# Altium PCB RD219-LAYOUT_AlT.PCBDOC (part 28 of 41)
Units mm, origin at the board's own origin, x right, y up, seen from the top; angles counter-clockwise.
Board outline 209.75 x 159.97 mm, 2 copper layers (TOP, BOTTOM), stack 0 mm thick; 398 components, 199 nets, 1469 pads, 0 vias.
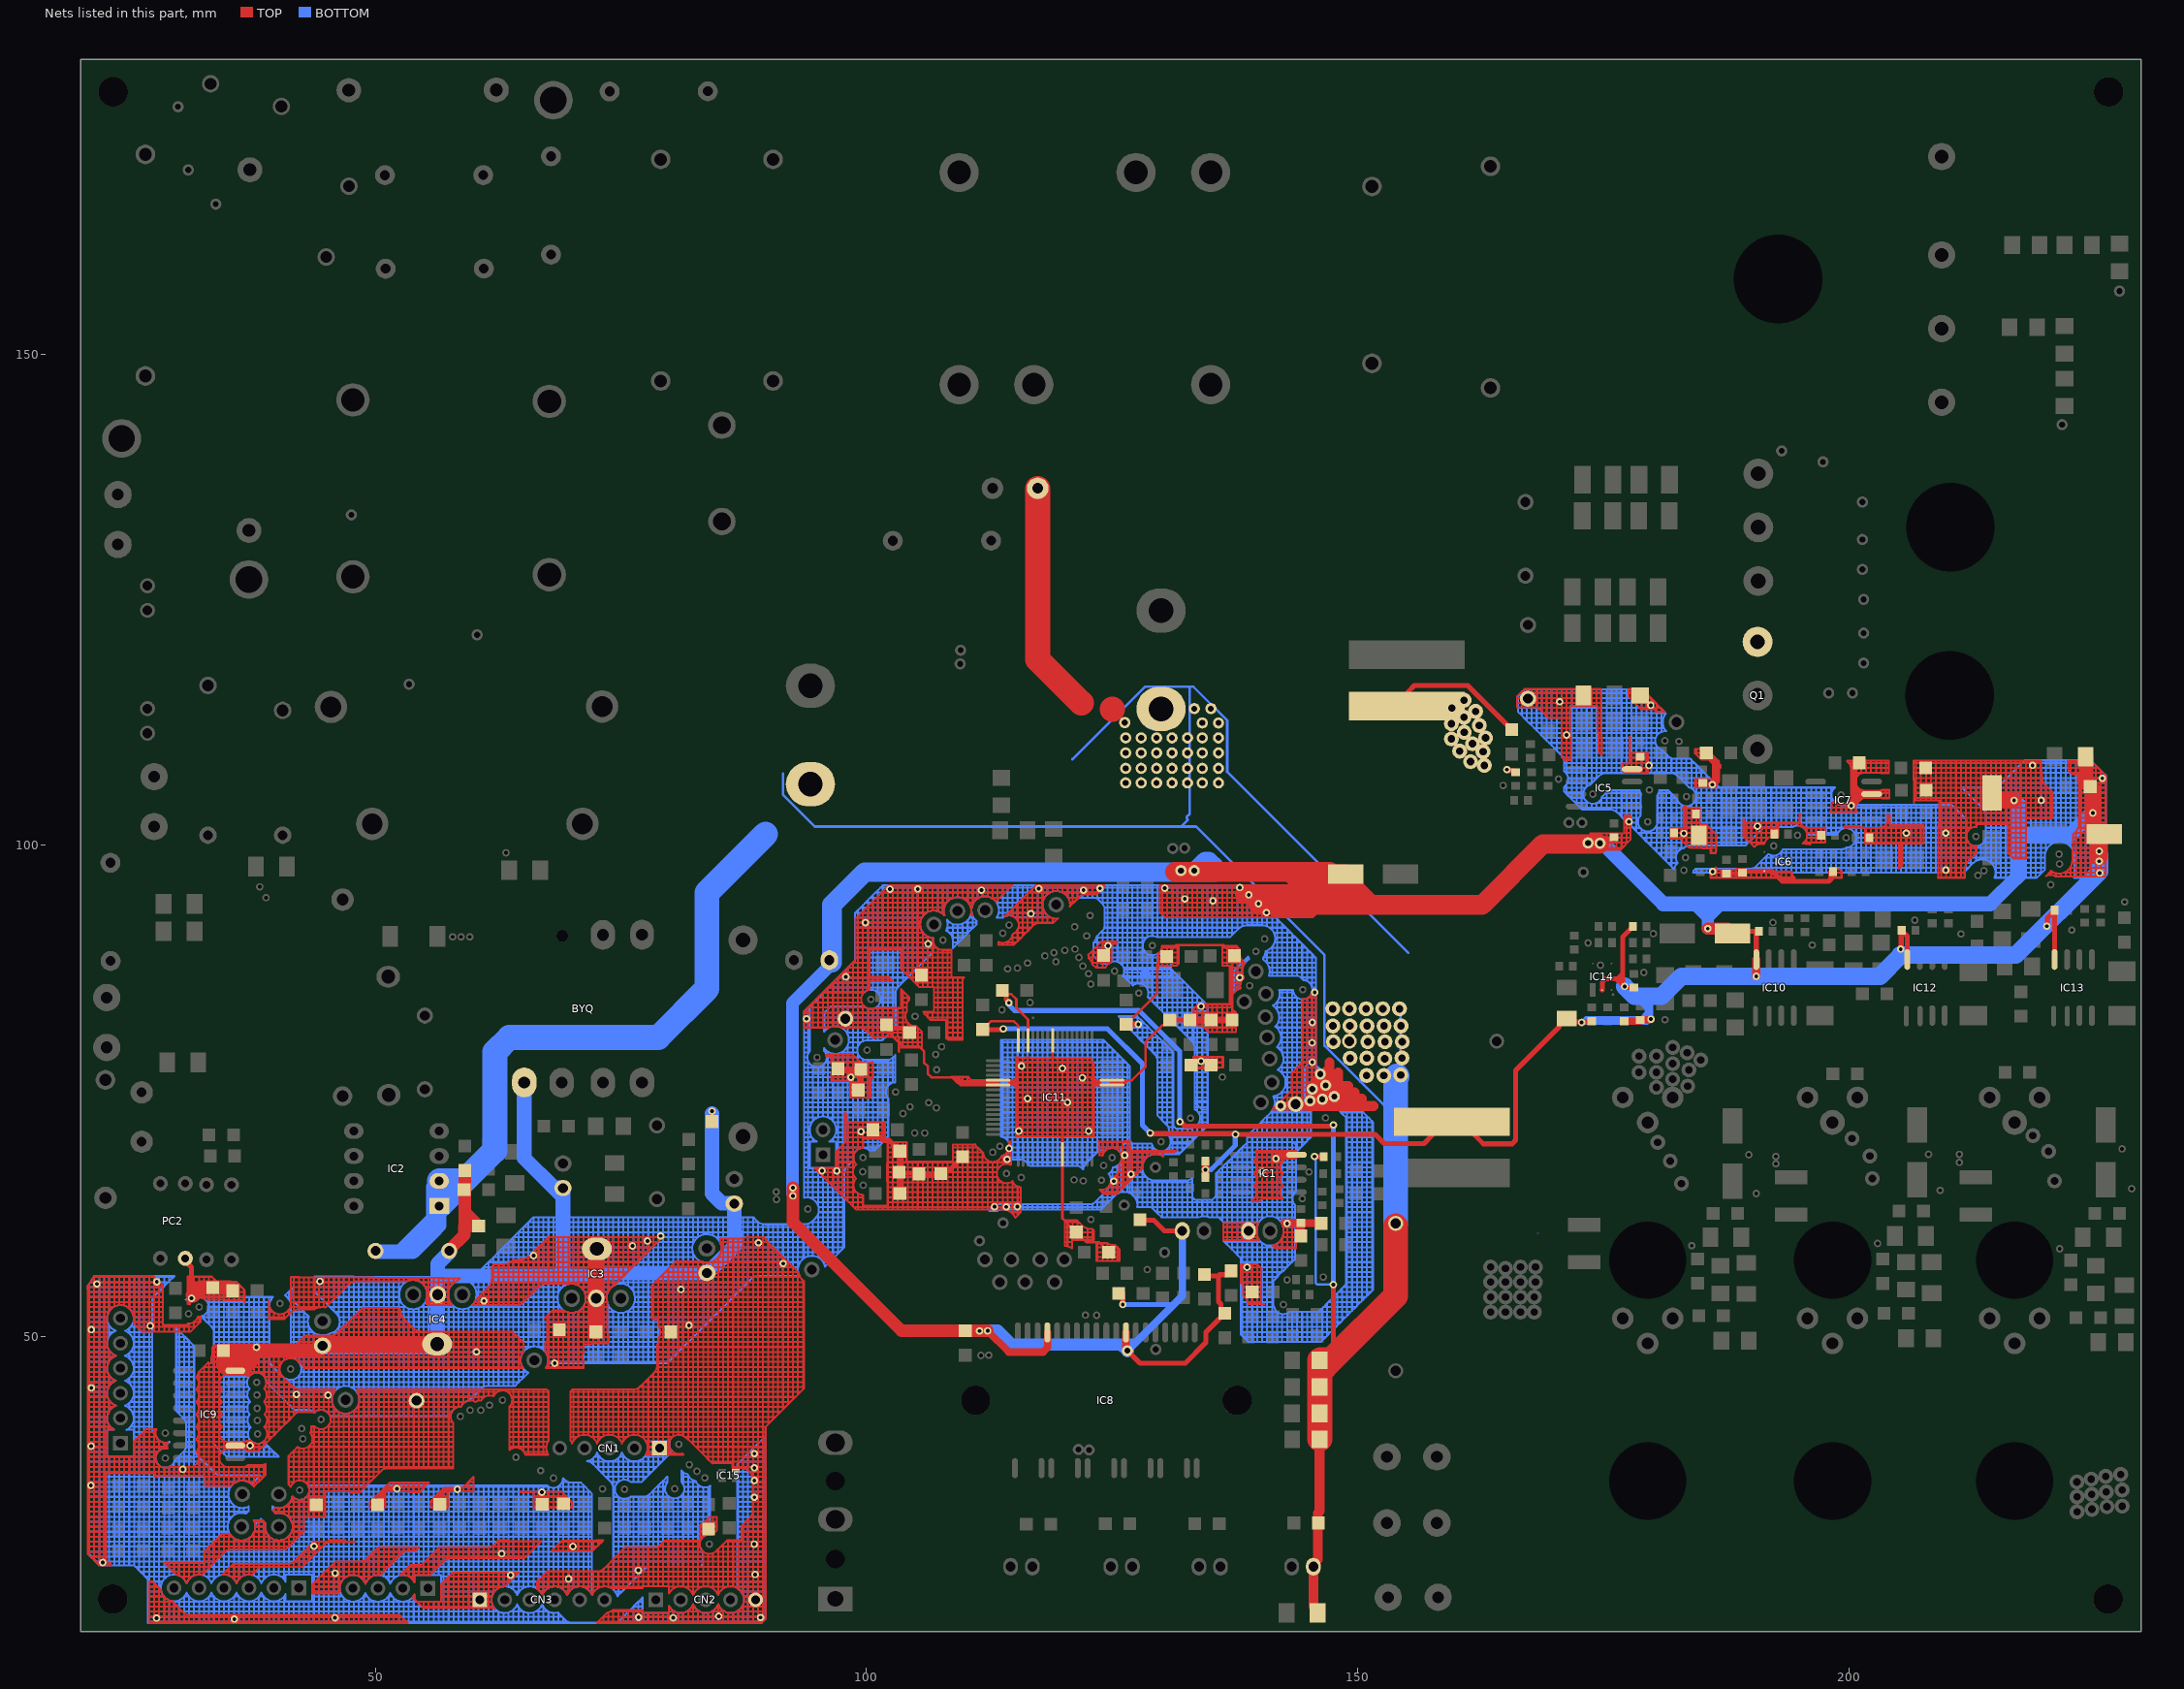
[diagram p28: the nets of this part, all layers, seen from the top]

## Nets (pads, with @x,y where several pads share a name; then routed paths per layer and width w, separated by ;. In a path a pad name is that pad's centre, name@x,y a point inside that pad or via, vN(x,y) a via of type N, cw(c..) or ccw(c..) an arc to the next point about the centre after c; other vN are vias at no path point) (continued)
GND: (continued)
  BOTTOM w0.203: 79.817,32.7 79.817,33.208 ; 79.817,32.7 80.325,32.7 ; 79.817,33.208 79.817,33.716 ; 79.817,33.208 80.325,33.208 ; 79.817,33.716 79.93,33.716 ; 79.817,33.716 79.817,33.804 ; 79.817,33.804 ccw(c80.475,34.534) 79.93,33.716 ; 79.817,37.921 79.817,38.288 ; 79.817,38.288 79.817,38.796 ; 79.817,38.796 79.817,39.304 ; 79.817,38.796 79.946,38.796 ; 79.817,39.304 79.817,39.337 ; 79.817,39.304 79.945,39.304 ; 79.817,39.337 79.955,39.337 ccw(c80.895,39.051) 79.945,39.304 ; 79.817,47.405 79.817,47.432 ; 79.817,47.405 79.844,47.432 ; 79.817,47.432 79.817,47.94 ; 79.817,47.432 79.844,47.432 ; 79.817,47.94 80.325,47.94 ; 79.817,47.94 79.817,48.448 ; 79.817,48.448 79.817,48.956 ; 79.817,48.448 80.325,48.448 ; 79.817,48.956 79.817,49.464 ; 79.817,48.956 80.325,48.956 ; 79.817,49.464 79.817,49.972 ; 79.817,49.464 80.325,49.464 ; 79.817,49.972 79.817,50.48 ; 79.817,49.972 80.325,49.972 ; 79.817,50.48 79.817,50.988 ; 79.817,50.48 80.325,50.48 ; 79.817,50.988 79.817,51.496 ; 79.817,50.988 80.325,50.988 ; 79.817,51.496 79.817,52.004 ; 79.817,51.496 80.325,51.496 ; 79.817,52.004 79.817,52.512 ; 79.817,52.004 80.325,52.004 ; 79.817,52.512 80.325,52.512 ; 79.817,52.512 79.817,53.02 ; 79.817,53.02 79.817,53.528 ; 79.817,53.02 80.325,53.02 ; 79.817,53.528 79.817,54.036 ; 79.817,53.528 80.325,53.528 ; 79.817,54.036 80.325,54.036 ; 79.817,54.036 79.817,54.544 ; 79.817,54.544 79.817,55.052 ; 79.817,54.544 80.325,54.544 ; 79.817,55.052 79.817,55.56 ; 79.817,55.052 80.325,55.052 ; 79.817,55.56 79.817,56.068 ; 79.817,55.56 80.325,55.56 ; 79.817,56.068 80.325,56.068 ; 79.817,56.068 79.817,56.489 79.817,56.576 ; 79.817,56.576 80.325,56.576 ; 79.817,56.576 79.817,57.084 ; 79.817,57.084 80.325,57.084 ; 79.817,57.084 79.817,57.592 ; 79.817,57.592 80.325,57.592 ; 79.817,57.592 79.817,58.1 ; 79.817,58.1 79.817,58.608 ; 79.817,58.1 80.325,58.1 ; 79.817,58.608 79.817,59.116 ; 79.817,58.608 80.325,58.608 ; 79.817,59.116 79.817,59.624 ; 79.817,59.116 80.325,59.116 ; 79.817,59.624 79.817,60.132 ; 79.817,59.624 80.325,59.624 ; 79.817,60.132 79.817,60.64 ; 79.817,60.132 80.325,60.132 ; 79.817,60.64 79.817,61.148 ; 79.817,60.64 80.325,60.64 ; 79.817,61.148 79.817,61.656 ; 79.817,61.148 80.325,61.148 ; 79.817,61.656 79.817,62.164 ; 79.817,61.656 80.325,61.656 ; 79.817,62.164 80.325,62.164 ; 79.844,47.432 80.325,47.913 ; 79.899,22.032 80.325,22.032 ; 79.899,22.032 79.899,22.597 ; 79.899,22.597 ccw(c81.087,23.241) 80.325,22.125 ; 79.93,33.716 ccw(c80.475,34.534) 80.322,33.563 ccw(c80.475,34.534) 80.325,33.563 ; 79.946,38.796 cw(c80.895,39.051) 79.945,39.304 ; 80.325,20.889 80.325,21.016 ; 80.325,20.889 80.833,20.889 ; 80.325,21.016 pad.@80.325,21.524 ; 80.325,21.016 80.833,21.016 ; pad.@80.325,21.524 80.325,22.032 ; pad.@80.325,21.524 80.833,21.524 ; 80.325,22.032 80.483,22.032 ; 80.325,22.032 80.325,22.125 ; 80.325,22.125 ccw(c81.087,23.241) 80.483,22.032 ; 80.325,26.571 80.325,26.604 ; 80.325,26.571 80.833,26.571 ; 80.325,26.604 80.325,27.112 ; 80.325,26.604 80.833,26.604 ; 80.325,27.112 80.325,27.62 ; 80.325,27.112 80.833,27.112 ; 80.325,27.62 80.325,28.128 ; 80.325,27.62 80.833,27.62 ; 80.325,28.128 80.325,28.636 ; 80.325,28.128 80.833,28.128 ; 80.325,28.636 80.325,29.144 ; 80.325,28.636 80.833,28.636 ; 80.325,29.144 80.325,29.652 ; 80.325,29.144 80.833,29.144 ; 80.325,29.652 80.325,30.16 ; 80.325,29.652 80.833,29.652 ; 80.325,30.16 80.325,30.668 ; 80.325,30.16 80.833,30.16 ; 80.325,30.668 80.325,31.176 ; 80.325,30.668 80.833,30.668 ; 80.325,31.176 80.325,31.684 ; 80.325,31.176 80.833,31.176 ; 80.325,31.684 80.325,32.192 ; 80.325,31.684 80.833,31.684 ; 80.325,32.192 80.325,32.7 ; 80.325,32.192 80.833,32.192 ; 80.325,32.7 80.325,33.208 ; 80.325,32.7 80.833,32.7 ; 80.325,33.208 80.833,33.208 ; 80.325,33.208 80.325,33.563 ; 80.325,33.563 ccw(c80.475,34.534) 80.827,33.616 ccw(c80.475,34.534) 80.833,33.618 ; 80.325,47.913 80.325,47.94 ; 80.325,47.913 80.352,47.94 ; 80.325,47.94 80.325,48.448 ; 80.325,47.94 80.352,47.94 ; 80.325,48.448 80.833,48.448 ; 80.325,48.448 80.325,48.956 ; 80.325,48.956 80.325,49.464 ; 80.325,48.956 80.833,48.956 ; 80.325,49.464 80.325,49.972 ; 80.325,49.464 80.833,49.464 ; 80.325,49.972 80.325,50.48 ; 80.325,49.972 80.833,49.972 ; 80.325,50.48 80.325,50.988 ; 80.325,50.48 80.833,50.48 ; 80.325,50.988 80.325,51.496 ; 80.325,50.988 80.833,50.988 ; 80.325,51.496 80.325,52.004 ; 80.325,51.496 80.833,51.496 ; 80.325,52.004 80.325,52.512 ; 80.325,52.004 80.833,52.004 ; 80.325,52.512 80.325,53.02 ; 80.325,52.512 80.833,52.512 ; 80.325,53.02 80.325,53.528 ; 80.325,53.02 80.833,53.02 ; 80.325,53.528 80.325,54.036 ; 80.325,53.528 80.833,53.528 ; 80.325,54.036 80.325,54.544 ; 80.325,54.036 80.833,54.036 ; 80.325,54.544 80.325,55.052 ; 80.325,54.544 80.833,54.544 ; 80.325,55.052 80.325,55.56 ; 80.325,55.052 pad.@80.833,55.052 ; 80.325,55.56 80.325,56.068 ; 80.325,55.56 80.833,55.56 ; 80.325,56.068 80.325,56.489 80.325,56.576 ; 80.325,56.068 80.833,56.068 ; 80.325,56.576 80.325,57.084 ; 80.325,56.576 80.833,56.576 ; 80.325,57.084 80.325,57.592 ; 80.325,57.084 80.833,57.084 ; 80.325,57.592 80.325,58.1 ; 80.325,57.592 80.833,57.592 ; 80.325,58.1 80.325,58.608 ; 80.325,58.1 80.833,58.1 ; 80.325,58.608 80.325,59.116 ; 80.325,58.608 80.833,58.608 ; 80.325,59.116 80.325,59.624 ; 80.325,59.116 80.833,59.116 ; 80.325,59.624 80.325,60.132 ; 80.325,59.624 80.833,59.624 ; 80.325,60.132 80.325,60.64 ; 80.325,60.132 80.833,60.132 ; 80.325,60.64 80.325,61.148 ; 80.325,60.64 80.833,60.64 ; 80.325,61.148 80.325,61.656 ; 80.325,61.148 80.833,61.148 ; 80.325,61.656 80.325,62.164 ; 80.325,61.656 80.833,61.656 ; 80.325,62.164 80.833,62.164 ; 80.352,47.94 80.833,48.421 ; 80.483,22.032 ccw(c81.087,23.241) 80.829,21.914 ccw(c81.087,23.241) 80.833,21.914 ; 80.833,20.889 80.833,21.016 ; 80.833,20.889 81.341,20.889 ; 80.833,21.016 80.833,21.524 ; 80.833,21.016 81.341,21.016 ; 80.833,21.524 81.341,21.524 ; 80.833,21.524 80.833,21.913 ; 80.833,21.914 ccw(c81.087,23.241) 81.341,21.913 ; 80.833,26.571 80.833,26.604 ; 80.833,26.571 81.341,26.571 ; 80.833,26.604 80.833,27.112 ; 80.833,26.604 81.341,26.604 ; 80.833,27.112 80.833,27.62 ; 80.833,27.112 81.341,27.112 ; 80.833,27.62 80.833,28.128 ; 80.833,27.62 81.341,27.62 ; 80.833,28.128 80.833,28.636 ; 80.833,28.128 81.341,28.128 ; 80.833,28.636 80.833,29.144 ; 80.833,28.636 81.341,28.636 ; 80.833,29.144 80.833,29.652 ; 80.833,29.144 81.341,29.144 ; 80.833,29.652 80.833,30.16 ; 80.833,29.652 81.341,29.652 ; 80.833,30.16 80.833,30.668 ; 80.833,30.16 81.341,30.16 ; 80.833,30.668 80.833,31.176 ; 80.833,30.668 81.341,30.668 ; 80.833,31.176 80.833,31.684 ; 80.833,31.176 81.341,31.176 ; 80.833,31.684 80.833,32.192 ; 80.833,31.684 81.341,31.684 ; 80.833,32.192 80.833,32.7 ; 80.833,32.192 81.341,32.192 ; 80.833,32.7 80.833,33.208 ; 80.833,32.7 81.341,32.7 ; 80.833,33.208 81.341,33.208 ; 80.833,33.208 80.833,33.618 ; 80.833,48.421 80.833,48.448 ; 80.833,48.421 80.86,48.448 ; 80.833,48.448 80.833,48.956 ; 80.833,48.448 80.86,48.448 ; 80.833,48.956 81.341,48.956 ; 80.833,48.956 80.833,49.464 ; 80.833,49.464 80.833,49.972 ; 80.833,49.464 81.341,49.464 ; 80.833,49.972 80.833,50.48 ; 80.833,49.972 81.341,49.972 ; 80.833,50.48 80.833,50.988 ; 80.833,50.48 81.341,50.48 ; 80.833,50.988 80.833,51.496 ; 80.833,50.988 81.341,50.988 ; 80.833,51.496 80.833,52.004 ; 80.833,51.496 81.341,51.496 ; 80.833,52.004 80.833,52.512 ; 80.833,52.004 81.341,52.004 ; 80.833,52.512 80.833,53.02 ; 80.833,52.512 81.341,52.512 ; 80.833,53.02 80.833,53.528 ; 80.833,53.02 81.341,53.02 ; 80.833,53.528 80.833,54.036 ; 80.833,53.528 81.341,53.528 ; 80.833,54.036 80.833,54.544 ; 80.833,54.036 81.341,54.036 ; 80.833,54.544 pad.@81.341,54.544 ; 80.833,54.544 pad.@80.833,55.052 ; pad.@80.833,55.052 80.833,55.56 ; pad.@80.833,55.052 pad.@81.341,55.052 ; 80.833,55.56 80.833,56.068 ; 80.833,55.56 81.341,55.56 ; 80.833,56.068 80.833,56.489 80.833,56.576 ; 80.833,56.068 81.341,56.068 ; 80.833,56.576 80.833,57.084 ; 80.833,56.576 81.341,56.576 ; 80.833,57.084 80.833,57.592 ; 80.833,57.084 81.341,57.084 ; 80.833,57.592 80.833,58.1 ; 80.833,57.592 81.341,57.592 ; 80.833,58.1 80.833,58.608 ; 80.833,58.1 81.341,58.1 ; 80.833,58.608 80.833,59.116 ; 80.833,58.608 81.341,58.608 ; 80.833,59.116 80.833,59.624 ; 80.833,59.116 81.341,59.116 ; 80.833,59.624 80.833,60.132 ; 80.833,59.624 81.341,59.624 ; 80.833,60.132 80.833,60.64 ; 80.833,60.132 81.341,60.132 ; 80.833,60.64 80.833,61.148 ; 80.833,60.64 81.341,60.64 ; 80.833,61.148 80.833,61.656 ; 80.833,61.148 81.341,61.148 ; 80.833,61.656 80.833,62.164 ; 80.833,61.656 81.341,61.656 ; 80.833,62.164 81.341,62.164 ; 80.86,48.448 81.341,48.929 ; 81.181,35.24 81.341,35.24 ; 81.181,35.24 81.181,35.748 ; 81.181,35.748 81.341,35.748 ; 81.181,35.748 81.181,36.256 ; 81.181,36.256 81.301,36.256 ; 81.301,36.256 ccw(c81.967,36.978) 81.341,36.221 ; 81.341,20.889 81.341,21.016 ; 81.341,20.889 81.849,20.889 ; 81.341,21.016 81.341,21.524 ; 81.341,21.016 81.849,21.016 ; 81.341,21.524 81.849,21.524 ; 81.341,21.524 81.341,21.913 ; 81.341,21.913 ccw(c81.087,23.241) 81.345,21.914 ccw(c81.087,23.241) 81.691,22.032 ; 81.341,26.571 81.849,26.571 ; 81.341,26.571 81.341,26.604 ; 81.341,26.604 81.849,26.604 ; 81.341,26.604 81.341,27.112 ; 81.341,27.112 81.341,27.62 ; 81.341,27.112 81.849,27.112 ; 81.341,27.62 81.341,28.128 ; 81.341,27.62 81.849,27.62 ; 81.341,28.128 81.849,28.128 ; 81.341,28.128 81.341,28.636 ; 81.341,28.636 81.341,29.144 ; 81.341,28.636 81.849,28.636 ; 81.341,29.144 81.341,29.652 ; 81.341,29.144 81.849,29.144 ; 81.341,29.652 81.849,29.652 ; 81.341,29.652 81.341,30.16 ; 81.341,30.16 81.341,30.668 ; 81.341,30.16 81.849,30.16 ; 81.341,30.668 81.341,31.176 ; 81.341,30.668 81.849,30.668 ; 81.341,31.176 81.341,31.684 ; 81.341,31.176 81.849,31.176 ; 81.341,31.684 81.341,32.192 ; 81.341,31.684 81.849,31.684 ; 81.341,32.192 81.341,32.7 ; 81.341,32.192 81.849,32.192 ; 81.341,32.7 81.341,33.208 ; 81.341,32.7 81.849,32.7 ; 81.341,33.208 81.341,33.716 ; 81.341,33.208 81.849,33.208 ; 81.341,33.716 81.849,33.716 ; 81.341,33.716 81.341,34.069 ; 81.341,34.069 ccw(c80.475,34.534) 81.408,34.224 ; 81.341,34.998 cw(c80.475,34.534) 81.438,34.732 ; 81.341,34.998 81.341,35.24 ; 81.341,35.24 81.341,35.748 ; 81.341,35.24 81.849,35.24 ; 81.341,35.748 81.849,35.748 ; 81.341,35.748 81.341,36.221 ; 81.341,48.929 81.368,48.956 ; 81.341,48.929 81.341,48.956 ; 81.341,48.956 81.368,48.956 ; 81.341,48.956 81.341,49.464 ; 81.341,49.464 81.849,49.464 ; 81.341,49.464 81.341,49.972 ; 81.341,49.972 81.341,50.48 ; 81.341,49.972 81.849,49.972 ; 81.341,50.48 81.341,50.988 ; 81.341,50.48 81.849,50.48 ; 81.341,50.988 81.341,51.496 ; 81.341,50.988 pad.@81.849,50.988 ; 81.341,51.496 81.341,52.004 ; 81.341,51.496 pad.@81.849,51.496 ; 81.341,52.004 81.341,52.512 ; 81.341,52.004 81.849,52.004 ; 81.341,52.512 81.341,53.02 ; 81.341,52.512 81.849,52.512 ; 81.341,53.02 81.341,53.528 ; 81.341,53.02 81.849,53.02 ; 81.341,53.528 81.341,54.036 ; 81.341,53.528 81.849,53.528 ; 81.341,54.036 pad.@81.341,54.544 ; 81.341,54.036 81.849,54.036 ; pad.@81.341,54.544 81.849,54.544 ; pad.@81.341,54.544 pad.@81.341,55.052 ; pad.@81.341,55.052 81.341,55.56 ; pad.@81.341,55.052 81.849,55.052 ; 81.341,55.56 81.341,56.068 ; 81.341,55.56 81.849,55.56 ; 81.341,56.068 81.341,56.489 81.341,56.576 ; 81.341,56.068 81.849,56.068 ; 81.341,56.576 81.341,57.084 ; 81.341,56.576 81.849,56.576 ; 81.341,57.084 81.341,57.592 ; 81.341,57.084 81.849,57.084 ; 81.341,57.592 81.341,58.1 ; 81.341,57.592 81.849,57.592 ; 81.341,58.1 81.341,58.608 ; 81.341,58.1 81.849,58.1 ; 81.341,58.608 81.341,59.116 ; 81.341,58.608 81.849,58.608 ; 81.341,59.116 81.341,59.624 ; 81.341,59.116 81.849,59.116 ; 81.341,59.624 81.341,60.132 ; 81.341,59.624 81.849,59.624 ; 81.341,60.132 81.341,60.64 ; 81.341,60.132 81.849,60.132 ; 81.341,60.64 81.341,61.148 ; 81.341,60.64 81.849,60.64 ; 81.341,61.148 81.341,61.656 ; 81.341,61.148 81.849,61.148 ; 81.341,61.656 81.341,62.164 ; 81.341,61.656 81.849,61.656 ; 81.341,62.164 81.849,62.164 ; 81.368,48.956 81.849,49.437 ; 81.408,34.224 ccw(c80.475,34.534) 81.41,34.23 ccw(c80.475,34.534) 81.458,34.534 ccw(c80.475,34.534) 81.438,34.732 ; 81.408,34.224 81.849,34.224 ; 81.438,34.732 81.849,34.732 ; 81.691,22.032 ccw(c81.087,23.241) 81.843,22.12 ccw(c81.087,23.241) 81.849,22.125 ; 81.691,22.032 81.849,22.032 ; 81.849,20.889 82.357,20.889 ; 81.849,20.889 81.849,21.016 ; 81.849,21.016 82.357,21.016 ; 81.849,21.016 81.849,21.524 ; 81.849,21.524 81.849,22.032 ; 81.849,21.524 82.357,21.524 ; 81.849,22.032 82.357,22.032 ; 81.849,22.032 81.849,22.125 ; 81.849,26.571 81.849,26.604 ; 81.849,26.571 82.357,26.571 ; 81.849,26.604 82.357,26.604 ; 81.849,26.604 81.849,27.112 ; 81.849,27.112 81.849,27.62 ; 81.849,27.112 82.357,27.112 ; 81.849,27.62 81.849,28.128 ; 81.849,27.62 82.357,27.62 ; 81.849,28.128 81.849,28.636 ; 81.849,28.128 82.357,28.128 ; 81.849,28.636 81.849,29.144 ; 81.849,28.636 82.357,28.636 ; 81.849,29.144 81.849,29.652 ; 81.849,29.144 82.357,29.144 ; 81.849,29.652 82.357,29.652 ; 81.849,29.652 81.849,30.16 ; 81.849,30.16 81.849,30.668 ; 81.849,30.16 82.357,30.16 ; 81.849,30.668 81.849,31.176 ; 81.849,30.668 82.357,30.668 ; 81.849,31.176 81.849,31.684 ; 81.849,31.176 82.357,31.176 ; 81.849,31.684 81.849,32.192 ; 81.849,31.684 82.357,31.684 ; 81.849,32.192 81.849,32.7 ; 81.849,32.192 82.357,32.192 ; 81.849,32.7 81.849,33.208 ; 81.849,32.7 82.357,32.7 ; 81.849,33.208 81.849,33.716 ; 81.849,33.208 82.357,33.208 ; 81.849,33.716 81.849,34.224 ; 81.849,33.716 82.357,33.716 ; 81.849,34.224 81.849,34.732 ; 81.849,34.224 82.357,34.224 ; 81.849,34.732 82.357,34.732 ; 81.849,34.732 81.849,35.24 ; 81.849,35.24 82.357,35.24 ; 81.849,35.24 81.849,35.748 ; 81.849,35.748 81.849,35.89 ; 81.849,35.748 81.931,35.748 ; 81.849,35.89 ccw(c82.737,36.311) 81.931,35.748 ; 81.849,49.437 81.876,49.464 ; 81.849,49.437 81.849,49.464 ; 81.849,49.464 81.876,49.464 ; 81.849,49.464 81.849,49.972 ; 81.849,49.972 82.357,49.972 ; 81.849,49.972 81.849,50.48 ; 81.849,50.48 pad.@81.849,50.988 ; 81.849,50.48 82.357,50.48 ; pad.@81.849,50.988 pad.@81.849,51.496 ; pad.@81.849,50.988 82.357,50.988 ; pad.@81.849,51.496 81.849,52.004 ; pad.@81.849,51.496 82.357,51.496 ; 81.849,52.004 81.849,52.512 ; 81.849,52.004 82.357,52.004 ; 81.849,52.512 81.849,53.02 ; 81.849,52.512 82.357,52.512 ; 81.849,53.02 81.849,53.528 ; 81.849,53.02 82.357,53.02 ; 81.849,53.528 81.849,54.036 ; 81.849,53.528 82.357,53.528 ; 81.849,54.036 81.849,54.544 ; 81.849,54.036 82.357,54.036 ; 81.849,54.544 81.849,55.052 ; 81.849,54.544 82.357,54.544 ; 81.849,55.052 81.849,55.56 ; 81.849,55.052 82.357,55.052 ; 81.849,55.56 81.849,56.068 ; 81.849,55.56 82.357,55.56 ; 81.849,56.068 81.849,56.489 81.849,56.576 ; 81.849,56.068 82.357,56.068 ; 81.849,56.576 81.849,57.084 ; 81.849,56.576 82.357,56.576 ; 81.849,57.084 81.849,57.592 ; 81.849,57.084 82.357,57.084 ; 81.849,57.592 81.849,58.1 ; 81.849,57.592 82.357,57.592 ; 81.849,58.1 81.849,58.608 ; 81.849,58.1 82.357,58.1 ; 81.849,58.608 81.849,59.116 ; 81.849,58.608 82.315,58.608 ; 81.849,59.116 81.849,59.624 ; 81.849,59.116 82.269,59.116 ; 81.849,59.624 82.357,59.624 ; 81.849,59.624 81.849,60.132 ; 81.849,60.132 81.849,60.64 ; 81.849,60.132 82.357,60.132 ; 81.849,60.64 81.849,61.148 ; 81.849,60.64 82.357,60.64 ; 81.849,61.148 81.849,61.656 ; 81.849,61.148 82.357,61.148 ; 81.849,61.656 81.849,62.164 ; 81.849,61.656 82.357,61.656 ; 81.849,62.164 82.357,62.164 ; 81.876,49.464 82.357,49.945 ; 81.931,35.748 ccw(c82.737,36.311) 82.353,35.406 ccw(c82.737,36.311) 82.357,35.405 ; 82.269,59.116 ccw(c83.691,58.989) 82.269,59.113 ccw(c83.691,58.989) 82.315,58.608 ; 82.269,59.116 cw(c83.691,58.989) 82.357,59.497 ; 82.315,58.608 ccw(c83.691,58.989) 82.357,58.481 ; 82.357,20.889 82.357,21.016 ; 82.357,20.889 82.865,20.889 ; 82.357,21.016 82.357,21.524 ; 82.357,21.016 82.865,21.016 ; 82.357,21.524 82.357,22.032 ; 82.357,21.524 82.865,21.524 ; 82.357,22.032 82.865,22.032 ; 82.357,22.032 82.357,22.54 ; 82.357,22.54 82.471,22.54 ; 82.357,22.54 82.357,22.778 ; 82.357,22.778 ccw(c83.627,23.241) 82.468,22.545 ccw(c83.627,23.241) 82.471,22.54 ; 82.357,26.571 82.357,26.604 ; 82.357,26.571 82.865,26.571 ; 82.357,26.604 82.357,27.112 ; 82.357,26.604 82.865,26.604 ; 82.357,27.112 82.357,27.62 ; 82.357,27.112 82.865,27.112 ; 82.357,27.62 82.357,28.128 ; 82.357,27.62 82.865,27.62 ; 82.357,28.128 82.357,28.636 ; 82.357,28.128 82.865,28.128 ; 82.357,28.636 82.357,29.144 ; 82.357,28.636 82.865,28.636 ; 82.357,29.144 82.357,29.652 ; 82.357,29.144 82.865,29.144 ; 82.357,29.652 82.357,30.16 ; 82.357,29.652 82.865,29.652 ; 82.357,30.16 82.357,30.668 ; 82.357,30.16 82.865,30.16 ; 82.357,30.668 82.357,31.176 ; 82.357,30.668 82.865,30.668 ; 82.357,31.176 82.357,31.684 ; 82.357,31.176 82.865,31.176 ; 82.357,31.684 82.357,32.192 ; 82.357,31.684 82.865,31.684 ; 82.357,32.192 82.357,32.7 ; 82.357,32.192 82.865,32.192 ; 82.357,32.7 82.357,33.208 ; 82.357,32.7 82.865,32.7 ; 82.357,33.208 82.357,33.716 ; 82.357,33.208 82.865,33.208 ; 82.357,33.716 82.357,34.224 ; 82.357,33.716 82.865,33.716 ; 82.357,34.224 82.357,34.732 ; 82.357,34.224 82.865,34.224 ; 82.357,34.732 82.357,35.24 ; 82.357,34.732 82.865,34.732 ; 82.357,35.24 82.655,35.24 ; 82.357,35.24 82.357,35.405 ; 82.357,49.945 82.384,49.972 ; 82.357,49.945 82.357,49.972 ; 82.357,49.972 82.357,50.48 ; 82.357,49.972 82.384,49.972 ; 82.357,50.48 82.865,50.48 ; 82.357,50.48 82.357,50.988 ; 82.357,50.988 82.865,50.988 ; 82.357,50.988 82.357,51.496 ; 82.357,51.496 82.357,52.004 ; 82.357,51.496 82.865,51.496 ; 82.357,52.004 82.357,52.512 ; 82.357,52.004 82.865,52.004 ; 82.357,52.512 82.357,53.02 ; 82.357,52.512 82.865,52.512 ; 82.357,53.02 82.357,53.528 ; 82.357,53.02 82.865,53.02 ; 82.357,53.528 82.357,54.036 ; 82.357,53.528 82.865,53.528 ; 82.357,54.036 82.357,54.544 ; 82.357,54.036 82.865,54.036 ; 82.357,54.544 82.357,55.052 ; 82.357,54.544 82.865,54.544 ; 82.357,55.052 82.357,55.56 ; 82.357,55.052 82.865,55.052 ; 82.357,55.56 82.357,56.068 ; 82.357,55.56 82.865,55.56 ; 82.357,56.068 82.357,56.489 82.357,56.576 ; 82.357,56.068 82.865,56.068 ; 82.357,56.576 82.357,57.084 ; 82.357,56.576 82.865,56.576 ; 82.357,57.084 82.357,57.592 ; 82.357,57.084 82.865,57.084 ; 82.357,57.592 82.357,58.1 ; 82.357,57.592 82.865,57.592 ; 82.357,58.1 82.357,58.481 ; 82.357,58.1 82.574,58.1 ; 82.357,58.481 ccw(c83.691,58.989) 82.358,58.478 ccw(c83.691,58.989) 82.574,58.1 ; 82.357,59.497 cw(c83.691,58.989) 82.358,59.5 cw(c83.691,58.989) 82.412,59.624 ; 82.357,59.497 82.357,59.624 ; 82.357,59.624 82.357,60.132 ; 82.357,59.624 82.412,59.624 ; 82.357,60.132 82.357,60.64 ; 82.357,60.132 82.836,60.132 ; 82.357,60.64 82.865,60.64 ; 82.357,60.64 82.357,61.148 ; 82.357,61.148 82.357,61.656 ; 82.357,61.148 82.865,61.148 ; 82.357,61.656 82.865,61.656 ; 82.357,61.656 82.357,62.164 ; 82.357,62.164 82.865,62.164 ; 82.384,49.972 82.865,50.453 ; 82.412,59.624 cw(c83.691,58.989) 82.836,60.132 ; 82.471,22.54 ccw(c83.627,23.241) 82.865,22.125 ; 82.574,58.1 ccw(c83.691,58.989) 82.581,58.091 ccw(c83.691,58.989) 82.865,57.825 ; 82.836,60.132 cw(c83.691,58.989) 82.865,60.153 ; 82.865,20.889 82.865,21.016 ; 82.865,20.889 83.373,20.889 ; 82.865,21.016 82.865,21.524 ; 82.865,21.016 83.373,21.016 ; 82.865,21.524 82.865,22.032 ; 82.865,21.524 83.373,21.524 ; 82.865,22.032 83.023,22.032 ; 82.865,22.032 82.865,22.125 ; 82.865,22.125 ccw(c83.627,23.241) 83.013,22.037 ccw(c83.627,23.241) 83.023,22.032 ; 82.865,26.571 82.865,26.604 ; 82.865,26.571 83.071,26.571 83.105,26.604 ; 82.865,26.604 83.105,26.604 ; 82.865,26.604 82.865,27.112 ; 82.865,27.112 82.865,27.62 ; 82.865,27.112 83.328,27.112 ; 82.865,27.62 82.865,28.128 ; 82.865,27.62 83.328,27.62 ; 82.865,28.128 82.865,28.636 ; 82.865,28.128 83.328,28.128 ; 82.865,28.636 82.865,29.144 ; 82.865,28.636 83.059,28.636 ; 82.865,29.144 82.865,29.652 ; 82.865,29.144 83.059,29.144 ; 82.865,29.652 83.373,29.652 ; 82.865,29.652 82.865,30.16 ; 82.865,30.16 82.865,30.668 ; 82.865,30.16 83.373,30.16 ; 82.865,30.668 82.865,31.176 ; 82.865,30.668 83.373,30.668 ; 82.865,31.176 82.865,31.684 ; 82.865,31.176 83.373,31.176 ; 82.865,31.684 82.865,32.192 ; 82.865,31.684 83.373,31.684 ; 82.865,32.192 82.865,32.7 ; 82.865,32.192 83.373,32.192 ; 82.865,32.7 82.865,33.208 ; 82.865,32.7 83.373,32.7 ; 82.865,33.208 82.865,33.716 ; 82.865,33.208 83.373,33.208 ; 82.865,33.716 82.865,34.224 ; 82.865,33.716 83.373,33.716 ; 82.865,34.224 82.865,34.732 ; 82.865,34.224 83.373,34.224 ; 82.865,34.732 83.182,34.732 ; 82.865,50.453 82.865,50.48 ; 82.865,50.453 82.892,50.48 ; 82.865,50.48 82.865,50.988 ; 82.865,50.48 82.892,50.48 ; 82.865,50.988 83.373,50.988 ; 82.865,50.988 82.865,51.496 ; 82.865,51.496 83.373,51.496 ; 82.865,51.496 82.865,52.004 ; 82.865,52.004 82.865,52.512 ; 82.865,52.004 83.373,52.004 ; 82.865,52.512 83.373,52.512 ; 82.865,52.512 82.865,53.02 ; 82.865,53.02 82.865,53.528 ; 82.865,53.02 83.373,53.02 ; 82.865,53.528 82.865,54.036 ; 82.865,53.528 83.373,53.528 ; 82.865,54.036 83.373,54.036 ; 82.865,54.036 82.865,54.544 ; 82.865,54.544 82.865,55.052 ; 82.865,54.544 83.373,54.544 ; 82.865,55.052 82.865,55.56 ; 82.865,55.052 83.373,55.052 ; 82.865,55.56 82.865,56.068 ; 82.865,55.56 83.373,55.56 ; 82.865,56.068 EC5.2@83.373,56.068 ; 82.865,56.068 82.865,56.489 82.865,56.576 ; 82.865,56.576 EC5.2@83.373,56.576 ; 82.865,56.576 82.865,57.084 ; 82.865,57.084 EC5.2@83.373,57.084 ; 82.865,57.084 82.865,57.592 ; 82.865,57.592 83.373,57.592 ; 82.865,57.592 82.865,57.825 ; 82.865,57.825 ccw(c83.691,58.989) 82.872,57.82 ccw(c83.691,58.989) 83.373,57.598 ; 82.865,60.153 cw(c83.691,58.989) 83.369,60.38 cw(c83.691,58.989) 83.373,60.38 ; 82.865,60.153 82.865,60.64 ; 82.865,60.64 82.865,61.148 ; 82.865,60.64 83.373,60.64 ; 82.865,61.148 82.865,61.656 ; 82.865,61.148 83.373,61.148 ; 82.865,61.656 82.865,62.164 ; 82.865,61.656 83.373,61.656 ; 82.865,62.164 83.373,62.164 ; 82.892,50.48 83.373,50.961 ; 83.023,22.032 ccw(c83.627,23.241) 83.369,21.914 ccw(c83.627,23.241) 83.373,21.914 ; 83.059,28.636 cw(c84.008,28.89) 83.025,28.89 cw(c84.008,28.89) 83.059,29.144 ; 83.059,29.144 cw(c84.008,28.89) 83.373,29.64 ; 83.105,26.604 83.328,26.828 83.328,27.112 ; 83.182,34.732 ccw(c83.551,35.642) 83.373,34.676 ; 83.328,27.112 83.328,27.62 ; 83.328,27.62 83.328,28.128 ; 83.373,20.889 83.373,21.016 ; 83.373,20.889 83.881,20.889 ; 83.373,21.016 83.373,21.524 ; 83.373,21.016 83.881,21.016 ; 83.373,21.524 83.881,21.524 ; 83.373,21.524 83.373,21.913 ; 83.373,21.914 ccw(c83.627,23.241) 83.881,21.913 ; 83.373,29.64 cw(c84.008,28.89) 83.388,29.652 ; 83.373,29.64 83.373,29.652 ; 83.373,29.652 83.373,30.16 ; 83.373,29.652 83.388,29.652 ; 83.373,30.16 83.373,30.668 ; 83.373,30.16 83.881,30.16 ; 83.373,30.668 83.373,31.176 ; 83.373,30.668 83.881,30.668 ; 83.373,31.176 83.373,31.684 ; 83.373,31.176 83.881,31.176 ; 83.373,31.684 83.373,32.192 ; 83.373,31.684 83.881,31.684 ; 83.373,32.192 83.373,32.7 ; 83.373,32.192 83.881,32.192 ; 83.373,32.7 83.373,33.208 ; 83.373,32.7 83.881,32.7 ; 83.373,33.208 83.373,33.716 ; 83.373,33.208 83.881,33.208 ; 83.373,33.716 83.373,34.224 ; 83.373,33.716 83.881,33.716 ; 83.373,34.224 83.881,34.224 ; 83.373,34.224 83.373,34.676 ; 83.373,34.676 ccw(c83.551,35.642) 83.881,34.717 ; 83.373,50.961 83.373,50.988 ; 83.373,50.961 83.4,50.988 ; 83.373,50.988 83.373,51.496 ; 83.373,50.988 83.4,50.988 ; 83.373,51.496 83.373,52.004 ; 83.373,51.496 83.881,51.496 ; 83.373,52.004 83.373,52.512 ; 83.373,52.004 83.881,52.004 ; 83.373,52.512 83.373,53.02 ; 83.373,52.512 83.881,52.512 ; 83.373,53.02 83.373,53.528 ; 83.373,53.02 83.881,53.02 ; 83.373,53.528 83.373,54.036 ; 83.373,53.528 83.881,53.528 ; 83.373,54.036 83.373,54.544 ; 83.373,54.036 83.881,54.036 ; 83.373,54.544 83.373,55.052 ; 83.373,54.544 83.881,54.544 ; 83.373,55.052 83.373,55.56 ; 83.373,55.052 83.881,55.052 ; 83.373,55.56 EC5.2@83.373,56.068 ; 83.373,55.56 83.881,55.56 ; EC5.2@83.373,56.068 EC5.2@83.881,56.068 ; EC5.2@83.373,56.068 83.373,56.489 EC5.2@83.373,56.576 ; EC5.2@83.373,56.576 EC5.2@83.373,57.084 ; EC5.2@83.373,56.576 EC5.2@83.881,56.576 ; EC5.2@83.373,57.084 83.373,57.592 ; EC5.2@83.373,57.084 EC5.2@83.881,57.084 ; 83.373,57.592 83.373,57.598 ; 83.373,57.592 83.399,57.592 ; 83.373,57.598 ccw(c83.691,58.989) 83.399,57.592 ; 83.373,60.38 cw(c83.691,58.989) 83.691,60.416 83.818,60.416 cw(c83.818,58.989) 83.881,60.415 ; 83.373,60.38 83.373,60.64 ; 83.373,60.64 83.881,60.64 ; 83.373,60.64 83.373,61.148 ; 83.373,61.148 83.373,61.656 ; 83.373,61.148 83.881,61.148 ; 83.373,61.656 83.881,61.656 ; 83.373,61.656 83.373,62.164 ; 83.373,62.164 83.881,62.164 ; 83.388,29.652 cw(c84.008,28.89) 83.881,29.864 ; 83.399,57.592 ccw(c83.691,58.989) 83.691,57.562 83.818,57.562 ccw(c83.818,58.989) 83.881,57.563 ; 83.4,50.988 83.881,51.469 ; 83.881,20.889 83.881,21.016 ; 83.881,20.889 84.389,20.889 ; 83.881,21.016 83.881,21.524 ; 83.881,21.016 84.389,21.016 ; 83.881,21.524 84.389,21.524 ; 83.881,21.524 83.881,21.913 ; 83.881,21.913 ccw(c83.627,23.241) 83.885,21.914 ccw(c83.627,23.241) 84.231,22.032 ; 83.881,29.864 cw(c84.008,28.89) 84.092,29.869 84.092,30.16 ; 83.881,29.864 83.881,30.16 ; 83.881,30.16 83.881,30.668 ; 83.881,30.16 84.092,30.16 ; 83.881,30.668 83.881,31.176 ; 83.881,30.668 84.092,30.668 ; 83.881,31.176 83.881,31.684 ; 83.881,31.176 84.092,31.176 ; 83.881,31.684 83.881,32.192 ; 83.881,31.684 84.092,31.684 ; 83.881,32.192 83.881,32.7 ; 83.881,32.192 84.092,32.192 ; 83.881,32.7 83.881,33.208 ; 83.881,32.7 84.092,32.7 ; 83.881,33.208 83.881,33.716 ; 83.881,33.208 84.092,33.208 ; 83.881,33.716 83.881,34.224 ; 83.881,33.716 84.092,33.716 ; 83.881,34.224 84.092,34.224 ; 83.881,34.224 83.881,34.717 ; 83.881,34.717 ccw(c83.551,35.642) 83.921,34.732 ; 83.881,51.469 83.881,51.496 ; 83.881,51.469 83.908,51.496 ; 83.881,51.496 83.881,52.004 ; 83.881,51.496 83.908,51.496 ; 83.881,52.004 84.389,52.004 ; 83.881,52.004 83.881,52.512 ; 83.881,52.512 83.881,53.02 ; 83.881,52.512 84.389,52.512 ; 83.881,53.02 83.881,53.528 ; 83.881,53.02 84.389,53.02 ; 83.881,53.528 83.881,54.036 ; 83.881,53.528 84.389,53.528 ; 83.881,54.036 83.881,54.544 ; 83.881,54.036 84.389,54.036 ; 83.881,54.544 83.881,55.052 ; 83.881,54.544 84.389,54.544 ; 83.881,55.052 83.881,55.56 ; 83.881,55.052 84.389,55.052 ; 83.881,55.56 EC5.2@83.881,56.068 ; 83.881,55.56 84.389,55.56 ; EC5.2@83.881,56.068 EC5.2@84.389,56.068 ; EC5.2@83.881,56.068 83.881,56.553 EC5.2@83.881,56.576 ; EC5.2@83.881,56.576 EC5.2@83.881,57.084 ; EC5.2@83.881,56.576 83.905,56.576 EC5.2@84.389,56.576 ; EC5.2@83.881,57.084 84.389,57.084 ; EC5.2@83.881,57.084 83.881,57.563 ; 83.881,57.563 ccw(c83.818,58.989) 84.109,57.592 ; 83.881,60.415 cw(c83.818,58.989) 84.389,60.297 ; 83.881,60.415 83.881,60.64 ; 83.881,60.64 83.881,61.148 ; 83.881,60.64 84.389,60.64 ; 83.881,61.148 83.881,61.656 ; 83.881,61.148 84.389,61.148 ; 83.881,61.656 83.881,62.164 ; 83.881,61.656 84.389,61.656 ; 83.881,62.164 84.389,62.164 ; 83.908,51.496 84.389,51.977 ; 83.921,34.732 ccw(c83.551,35.642) 84.092,34.822 ; 83.921,34.732 84.092,34.732 ; 84.092,30.16 84.092,30.668 ; 84.092,30.668 84.092,31.176 ; 84.092,31.176 84.092,31.684 ; 84.092,31.684 84.092,32.192 ; 84.092,32.192 84.092,32.7 ; 84.092,32.7 84.092,33.208 ; 84.092,33.208 84.092,33.716 ; 84.092,33.716 84.092,34.224 ; 84.092,34.224 84.092,34.732 ; 84.092,34.732 84.092,34.822 ; 84.109,57.592 ccw(c83.818,58.989) 84.114,57.593 ccw(c83.818,58.989) 84.389,57.681 ; 84.109,57.592 84.389,57.592 ; 84.231,22.032 ccw(c83.627,23.241) 84.383,22.12 ccw(c83.627,23.241) 84.389,22.125 ; 84.231,22.032 84.389,22.032 ; 84.389,20.889 84.897,20.889 ; 84.389,20.889 84.389,21.016 ; 84.389,21.016 84.897,21.016 ; 84.389,21.016 84.389,21.524 ; 84.389,21.524 pad.@84.897,21.524 ; 84.389,21.524 84.389,22.032 ; 84.389,22.032 84.897,22.032 ; 84.389,22.032 84.389,22.125 ; 84.389,51.977 84.389,52.004 ; 84.389,51.977 84.416,52.004 ; 84.389,52.004 84.416,52.004 ; 84.389,52.004 84.389,52.512 ; 84.389,52.512 84.897,52.512 ; 84.389,52.512 84.389,53.02 ; 84.389,53.02 84.389,53.528 ; 84.389,53.02 84.897,53.02 ; 84.389,53.528 84.389,54.036 ; 84.389,53.528 84.897,53.528 ; 84.389,54.036 84.897,54.036 ; 84.389,54.036 84.389,54.544 ; 84.389,54.544 84.389,55.052 ; 84.389,54.544 84.897,54.544 ; 84.389,55.052 84.389,55.56 ; 84.389,55.052 84.897,55.052 ; 84.389,55.56 EC5.2@84.389,56.068 ; 84.389,55.56 84.897,55.56 ; EC5.2@84.389,56.068 84.897,56.068 ; EC5.2@84.389,56.068 EC5.2@84.389,56.576 ; EC5.2@84.389,56.576 84.389,57.061 84.389,57.084 ; EC5.2@84.389,56.576 84.897,56.576 ; 84.389,57.084 84.413,57.084 84.897,57.084 ; 84.389,57.084 84.389,57.592 ; 84.389,57.592 84.897,57.592 ; 84.389,57.592 84.389,57.681 ; 84.389,57.681 ccw(c83.818,58.989) 84.398,57.685 ccw(c83.818,58.989) 84.897,58.056 ; 84.389,60.297 cw(c83.818,58.989) 84.398,60.293 cw(c83.818,58.989) 84.672,60.132 ; 84.389,60.297 84.389,60.64 ; 84.389,60.64 84.389,61.148 ; 84.389,60.64 84.897,60.64 ; 84.389,61.148 84.389,61.656 ; 84.389,61.148 84.897,61.148 ; 84.389,61.656 84.389,62.164 ; 84.389,61.656 84.897,61.656 ; 84.389,62.164 84.897,62.164 ; 84.416,52.004 84.897,52.485 ; 84.672,60.132 84.897,60.132 ; 84.897,20.889 84.897,21.016 ; 84.897,20.889 85.405,20.889 ; 84.897,21.016 pad.@84.897,21.524 ; 84.897,21.016 85.405,21.016 ; pad.@84.897,21.524 84.897,22.032 ; pad.@84.897,21.524 85.405,21.524 ; 84.897,22.032 84.897,22.54 ; 84.897,22.032 85.405,22.032 ; 84.897,22.54 84.897,22.778 ; 84.897,22.54 85.011,22.54 ; 84.897,22.778 ccw(c86.167,23.241) 85.008,22.545 ccw(c86.167,23.241) 85.011,22.54 ; 84.897,52.485 84.924,52.512 ; 84.897,52.485 84.897,52.512 ; 84.897,52.512 84.897,53.02 ; 84.897,52.512 84.924,52.512 ; 84.897,53.02 85.405,53.02 ; 84.897,53.02 84.897,53.528 ; 84.897,53.528 84.897,54.036 ; 84.897,53.528 85.405,53.528 ; 84.897,54.036 84.897,54.544 ; 84.897,54.036 85.405,54.036 ; 84.897,54.544 84.897,55.052 ; 84.897,54.544 85.405,54.544 ; 84.897,55.052 84.897,55.56 ; 84.897,55.052 85.405,55.052 ; 84.897,55.56 84.897,56.068 ; 84.897,55.56 85.405,55.56 ; 84.897,56.068 84.897,56.576 ; 84.897,56.068 85.405,56.068 ; 84.897,56.576 84.897,57.084 ; 84.897,56.576 85.405,56.576 ; 84.897,57.084 84.897,57.569 84.897,57.592 ; 84.897,57.084 85.405,57.084 ; 84.897,57.592 84.921,57.592 85.405,57.592 ; 84.897,57.592 84.897,58.056 ; 84.897,58.056 ccw(c83.818,58.989) 84.934,58.1 ; 84.897,60.132 84.897,60.64 ; 84.897,60.132 85.405,60.132 ; 84.897,60.64 84.897,61.148 ; 84.897,60.64 85.405,60.64 ; 84.897,61.148 84.897,61.656 ; 84.897,61.148 85.405,61.148 ; 84.897,61.656 84.897,62.164 ; 84.897,61.656 85.405,61.656 ; 84.897,62.164 85.405,62.164 ; 84.924,52.512 85.405,52.993 ; 84.934,58.1 ccw(c83.818,58.989) 85.193,58.608 ; 84.934,58.1 85.405,58.1 ; 85.096,59.624 cw(c83.818,58.989) 85.1,59.615 cw(c83.818,58.989) 85.239,59.116 ; 85.096,59.624 85.405,59.624 ; 85.193,58.608 ccw(c83.818,58.989) 85.196,58.62 ccw(c83.818,58.989) 85.245,58.989 ccw(c83.818,58.989) 85.239,59.116 ; 85.193,58.608 85.405,58.608 ; 85.239,59.116 85.405,59.116 ; 85.405,20.889 85.405,21.016 ; 85.405,20.889 85.913,20.889 ; 85.405,21.016 85.405,21.524 ; 85.405,21.016 85.913,21.016 ; 85.405,21.524 85.913,21.524 ; 85.405,21.524 85.405,22.032 ; 85.405,22.032 85.563,22.032 ; 85.405,52.993 85.405,53.02 ; 85.405,52.993 85.432,53.02 ; 85.405,53.02 85.405,53.528 ; 85.405,53.02 85.432,53.02 ; 85.405,53.528 85.913,53.528 ; 85.405,53.528 85.405,54.036 ; 85.405,54.036 85.405,54.544 ; 85.405,54.036 85.913,54.036 ; 85.405,54.544 85.405,55.052 ; 85.405,54.544 85.913,54.544 ; 85.405,55.052 85.405,55.56 ; 85.405,55.052 85.913,55.052 ; 85.405,55.56 85.405,56.068 ; 85.405,55.56 85.913,55.56 ; 85.405,56.068 85.405,56.576 ; 85.405,56.068 85.913,56.068 ; 85.405,56.576 85.405,57.084 ; 85.405,56.576 85.913,56.576 ; 85.405,57.084 85.405,57.592 ; 85.405,57.084 85.913,57.084 ; 85.405,57.592 85.405,58.076 85.405,58.1 ; 85.405,57.592 85.913,57.592 ; 85.405,58.1 85.429,58.1 85.913,58.1 ; 85.405,58.1 85.405,58.608 ; 85.405,58.608 85.405,59.116 ; 85.405,58.608 85.913,58.608 ; 85.405,59.116 85.405,59.624 ; 85.405,59.116 85.913,59.116 ; 85.405,59.624 85.405,60.132 ; 85.405,59.624 85.913,59.624 ; 85.405,60.132 85.405,60.64 ; 85.405,60.132 85.913,60.132 ; 85.405,60.64 85.405,61.148 ; 85.405,60.64 85.913,60.64 ; 85.405,61.148 85.405,61.656 ; 85.405,61.148 85.913,61.148 ; 85.405,61.656 85.405,62.164 ; 85.405,61.656 85.913,61.656 ; 85.405,62.164 85.913,62.164 ; 85.432,53.02 85.913,53.501 ; 85.563,22.032 ccw(c86.167,23.241) 85.909,21.914 ccw(c86.167,23.241) 85.913,21.914 ; 85.913,20.889 85.913,21.016 ; 85.913,20.889 86.421,20.889 ; 85.913,21.016 85.913,21.524 ; 85.913,21.016 86.421,21.016 ; 85.913,21.524 86.421,21.524 ; 85.913,21.524 85.913,21.913 ; 85.913,21.914 ccw(c86.167,23.241) 86.421,21.913 ; 85.913,53.501 85.94,53.528 ; 85.913,53.501 85.913,53.528 ; 85.913,53.528 85.94,53.528 ; 85.913,53.528 85.913,54.036 ; 85.913,54.036 86.421,54.036 ; 85.913,54.036 85.913,54.544 ; 85.913,54.544 85.913,55.052 ; 85.913,54.544 86.421,54.544 ; 85.913,55.052 85.913,55.56 ; 85.913,55.052 86.421,55.052 ; 85.913,55.56 85.913,56.068 ; 85.913,55.56 86.421,55.56 ; 85.913,56.068 86.421,56.068 ; 85.913,56.068 85.913,56.576 ; 85.913,56.576 86.421,56.576 ; 85.913,56.576 85.913,57.084 ; 85.913,57.084 86.421,57.084 ; 85.913,57.084 85.913,57.592 ; 85.913,57.592 85.913,58.1 ; 85.913,57.592 86.421,57.592 ; 85.913,58.1 86.421,58.1 ; 85.913,58.1 85.913,58.584 85.913,58.608 ; 85.913,58.608 85.937,58.608 86.421,58.608 ; 85.913,58.608 85.913,59.116 ; 85.913,59.116 86.421,59.116 ; 85.913,59.116 85.913,59.624 ; 85.913,59.624 85.913,60.132 ; 85.913,59.624 86.421,59.624 ; 85.913,60.132 85.913,60.64 ; 85.913,60.132 86.421,60.132 ; 85.913,60.64 86.421,60.64 ; 85.913,60.64 85.913,61.148 ; 85.913,61.148 85.913,61.656 ; 85.913,61.148 86.421,61.148 ; 85.913,61.656 86.421,61.656 ; 85.913,61.656 85.913,62.164 ; 85.913,62.164 86.421,62.164 ; 85.94,53.528 86.421,54.009 ; 86.421,20.889 86.421,21.016 ; 86.421,20.889 86.929,20.889 ; 86.421,21.016 86.421,21.524 ; 86.421,21.016 86.929,21.016 ; 86.421,21.524 86.929,21.524 ; 86.421,21.524 86.421,21.913 ; 86.421,21.913 ccw(c86.167,23.241) 86.425,21.914 ccw(c86.167,23.241) 86.771,22.032 ; 86.421,54.009 86.421,54.036 ; 86.421,54.009 86.448,54.036 ; 86.421,54.036 86.448,54.036 ; 86.421,54.036 86.421,54.544 ; 86.421,54.544 86.929,54.544 ; 86.421,54.544 86.421,55.052 ; 86.421,55.052 86.421,55.56 ; 86.421,55.052 86.929,55.052 ; 86.421,55.56 86.421,56.068 ; 86.421,55.56 86.929,55.56 ; 86.421,56.068 86.421,56.576 ; 86.421,56.068 86.929,56.068 ; 86.421,56.576 86.421,57.084 ; 86.421,56.576 86.929,56.576 ; 86.421,57.084 86.421,57.592 ; 86.421,57.084 86.929,57.084 ; 86.421,57.592 86.421,58.1 ; 86.421,57.592 86.929,57.592 ; 86.421,58.1 86.929,58.1 ; 86.421,58.1 86.421,58.608 ; 86.421,58.608 86.421,59.092 86.421,59.116 ; 86.421,58.608 86.929,58.608 ; 86.421,59.116 86.421,59.624 ; 86.421,59.116 86.445,59.116 86.929,59.116 ; 86.421,59.624 86.421,60.132 ; 86.421,59.624 86.592,59.624 86.929,59.624 ; 86.421,60.132 86.592,60.132 86.929,60.132 ; 86.421,60.132 86.421,60.64 ; 86.421,60.64 86.592,60.64 86.929,60.64 ; 86.421,60.64 86.421,61.148 ; 86.421,61.148 86.421,61.656 ; 86.421,61.148 86.541,61.148 86.929,61.148 ; 86.421,61.656 86.421,62.164 ; 86.421,61.656 86.541,61.656 86.929,61.656 ; 86.421,62.164 86.541,62.164 86.929,62.164 ; 86.448,54.036 86.929,54.517 ; 86.771,22.032 ccw(c86.167,23.241) 86.923,22.12 ccw(c86.167,23.241) 86.929,22.125 ; 86.771,22.032 86.929,22.032 ; 86.846,24.41 cw(c86.167,23.241) 86.929,24.357 ; 86.846,24.41 86.846,24.572 ; 86.846,24.572 86.929,24.572 ; 86.846,24.572 86.846,25.08 ; 86.846,25.08 86.929,25.08 ; 86.846,25.08 86.846,25.588 ; 86.846,25.588 86.929,25.588 ; 86.846,25.588 86.846,26.096 ; 86.846,26.096 86.929,26.096 ; 86.846,26.096 86.846,26.604 ; 86.846,26.604 86.929,26.604 ; 86.846,26.604 86.846,27.112 ; 86.846,27.112 86.929,27.112 ; 86.846,27.112 86.846,27.62 ; 86.846,27.62 86.929,27.62 ; 86.846,27.62 86.846,28.128 ; 86.846,28.128 86.929,28.128 ; 86.846,28.128 86.846,28.636 ; 86.846,28.636 86.929,28.636 ; 86.846,28.636 86.846,29.144 ; 86.846,29.144 86.929,29.144 ; 86.846,29.144 86.846,29.652 ; 86.846,29.652 86.929,29.652 ; 86.846,29.652 86.846,30.16 ; 86.846,30.16 86.929,30.16 ; 86.846,30.16 86.846,30.668 ; 86.846,30.668 86.929,30.668 ; 86.846,30.668 86.846,31.176 ; 86.846,31.176 86.929,31.176 ; 86.846,31.176 86.846,31.684 ; 86.846,31.684 86.929,31.684 ; 86.846,31.684 86.846,32.192 ; 86.846,32.192 86.929,32.192 ; 86.846,32.192 86.846,32.7 ; 86.846,32.7 86.929,32.7 ; 86.846,32.7 86.846,33.208 ; 86.846,33.208 86.929,33.208 ; 86.846,33.208 86.846,33.716 ; 86.846,33.716 86.929,33.716 ; 86.846,33.716 86.846,34.224 ; 86.846,34.224 86.929,34.224 ; 86.846,34.224 86.846,34.732 ; 86.846,34.732 86.929,34.732 ; 86.846,34.732 86.846,35.24 ; 86.846,35.24 86.929,35.24 ; 86.846,35.24 86.846,35.748 ; 86.846,35.748 86.929,35.748 ; 86.846,35.748 86.846,36.256 ; 86.846,36.256 86.929,36.256 ; 86.846,36.256 86.846,36.764 ; 86.846,36.764 86.929,36.764 ; 86.846,36.764 86.846,37.027 87.091,37.272 ; 86.929,20.889 86.929,21.016 ; 86.929,20.889 87.437,20.889 ; 86.929,21.016 86.929,21.524 ; 86.929,21.016 87.437,21.016 ; 86.929,21.524 86.929,22.032 ; 86.929,21.524 87.437,21.524 ; 86.929,22.032 87.437,22.032 ; 86.929,22.032 86.929,22.125 ; 86.929,24.357 86.929,24.572 ; 86.929,24.572 87.437,24.572 ; 86.929,24.572 86.929,25.08 ; 86.929,25.08 86.929,25.588 ; 86.929,25.08 87.437,25.08 ; 86.929,25.588 86.929,26.096 ; 86.929,25.588 87.437,25.588 ; 86.929,26.096 86.929,26.604 ; 86.929,26.096 87.437,26.096 ; 86.929,26.604 86.929,27.112 ; 86.929,26.604 87.437,26.604 ; 86.929,27.112 86.929,27.62 ; 86.929,27.112 87.437,27.112 ; 86.929,27.62 86.929,28.128 ; 86.929,27.62 87.437,27.62 ; 86.929,28.128 86.929,28.636 ; 86.929,28.128 87.437,28.128 ; 86.929,28.636 86.929,29.144 ; 86.929,28.636 87.437,28.636 ; 86.929,29.144 86.929,29.652 ; 86.929,29.144 87.437,29.144 ; 86.929,29.652 86.929,30.16 ; 86.929,29.652 87.437,29.652 ; 86.929,30.16 86.929,30.668 ; 86.929,30.16 87.437,30.16 ; 86.929,30.668 86.929,31.176 ; 86.929,30.668 87.437,30.668 ; 86.929,31.176 86.929,31.684 ; 86.929,31.176 87.437,31.176 ; 86.929,31.684 86.929,32.192 ; 86.929,31.684 87.437,31.684 ; 86.929,32.192 86.929,32.7 ; 86.929,32.192 87.437,32.192 ; 86.929,32.7 86.929,33.208 ; 86.929,32.7 87.437,32.7 ; 86.929,33.208 86.929,33.716 ; 86.929,33.208 87.437,33.208 ; 86.929,33.716 86.929,34.224 ; 86.929,33.716 87.437,33.716 ; 86.929,34.224 86.929,34.732 ; 86.929,34.224 87.437,34.224 ; 86.929,34.732 86.929,35.24 ; 86.929,34.732 87.437,34.732 ; 86.929,35.24 86.929,35.748 ; 86.929,35.24 87.437,35.24 ; 86.929,35.748 86.929,36.256 ; 86.929,35.748 87.437,35.748 ; 86.929,36.256 86.929,36.764 ; 86.929,36.256 87.437,36.256 ; 86.929,36.764 87.437,36.764 ; 86.929,54.517 86.929,54.544 ; 86.929,54.517 86.956,54.544 ; 86.929,54.544 86.929,55.052 ; 86.929,54.544 86.956,54.544 ; 86.929,55.052 87.437,55.052 ; 86.929,55.052 86.929,55.56 ; 86.929,55.56 86.929,56.068 ; 86.929,55.56 87.437,55.56 ; 86.929,56.068 86.929,56.576 ; 86.929,56.068 87.437,56.068 ; 86.929,56.576 86.929,57.084 ; 86.929,56.576 87.437,56.576 ; 86.929,57.084 86.929,57.592 ; 86.929,57.084 87.437,57.084 ; 86.929,57.592 86.929,58.1 ; 86.929,57.592 87.437,57.592 ; 86.929,58.1 86.929,58.608 ; 86.929,58.1 87.437,58.1 ; 86.929,58.608 86.929,59.116 ; 86.929,58.608 87.437,58.608 ; 86.929,59.116 86.929,59.624 ; 86.929,59.116 87.437,59.116 ; 86.929,59.624 86.929,60.132 ; 86.929,59.624 87.437,59.624 ; 86.929,60.132 86.929,60.64 ; 86.929,60.132 87.437,60.132 ; 86.929,60.64 86.929,61.148 ; 86.929,60.64 87.437,60.64 ; 86.929,61.148 86.929,61.656 ; 86.929,61.148 87.437,61.148 ; 86.929,61.656 86.929,62.164 ; 86.929,61.656 87.437,61.656 ; 86.929,62.164 87.437,62.164 ; 86.956,54.544 87.437,55.025 ; 87.091,37.272 87.437,37.272 ; 87.091,37.272 87.437,37.618 ; 87.437,20.889 87.437,21.016 ; 87.437,20.889 87.945,20.889 ; 87.437,21.016 87.437,21.524 ; 87.437,21.016 87.945,21.016 ; 87.437,21.524 87.437,22.032 ; 87.437,21.524 87.945,21.524 ; 87.437,22.032 87.437,22.54 ; 87.437,22.032 87.945,22.032 ; 87.437,22.54 87.945,22.54 ; 87.437,22.54 87.437,22.778 ; 87.437,22.779 ccw(c86.167,23.241) 87.505,23.048 ; 87.437,23.704 cw(c86.167,23.241) 87.481,23.556 ; 87.437,23.704 87.437,24.064 ; 87.437,24.064 87.437,24.572 ; 87.437,24.064 87.945,24.064 ; 87.437,24.572 87.437,25.08 ; 87.437,24.572 87.945,24.572 ; 87.437,25.08 87.437,25.588 ; 87.437,25.08 87.945,25.08 ; 87.437,25.588 87.437,26.096 ; 87.437,25.588 87.945,25.588 ; 87.437,26.096 87.437,26.604 ; 87.437,26.096 87.945,26.096 ; 87.437,26.604 87.437,27.112 ; 87.437,26.604 87.945,26.604 ; 87.437,27.112 87.437,27.62 ; 87.437,27.112 87.945,27.112 ; 87.437,27.62 87.437,28.128 ; 87.437,27.62 87.945,27.62 ; 87.437,28.128 87.437,28.636 ; 87.437,28.128 87.945,28.128 ; 87.437,28.636 87.437,29.144 ; 87.437,28.636 87.945,28.636 ; 87.437,29.144 87.437,29.652 ; 87.437,29.144 87.945,29.144 ; 87.437,29.652 87.437,30.16 ; 87.437,29.652 87.945,29.652 ; 87.437,30.16 87.437,30.668 ; 87.437,30.16 87.945,30.16 ; 87.437,30.668 87.437,31.176 ; 87.437,30.668 87.945,30.668 ; 87.437,31.176 87.437,31.684 ; 87.437,31.176 87.945,31.176 ; 87.437,31.684 87.437,32.192 ; 87.437,31.684 87.945,31.684 ; 87.437,32.192 87.437,32.7 ; 87.437,32.192 87.945,32.192 ; 87.437,32.7 87.437,33.208 ; 87.437,32.7 87.945,32.7 ; 87.437,33.208 87.437,33.716 ; 87.437,33.208 87.945,33.208 ; 87.437,33.716 87.437,34.224 ; 87.437,33.716 87.945,33.716 ; 87.437,34.224 87.437,34.732 ; 87.437,34.224 87.945,34.224 ; 87.437,34.732 87.437,35.24 ; 87.437,34.732 87.945,34.732 ; 87.437,35.24 87.437,35.748 ; 87.437,35.24 87.945,35.24 ; 87.437,35.748 87.437,36.256 ; 87.437,35.748 87.945,35.748 ; 87.437,36.256 87.437,36.764 ; 87.437,36.256 87.945,36.256 ; 87.437,36.764 87.437,37.272 ; 87.437,36.764 87.945,36.764 ; 87.437,37.272 87.437,37.618 ; 87.437,37.272 87.945,37.272 ; 87.437,37.618 87.599,37.78 ; 87.437,55.025 87.437,55.052 ; 87.437,55.025 87.464,55.052 ; 87.437,55.052 87.464,55.052 ; 87.437,55.052 87.437,55.56 ; 87.437,55.56 87.945,55.56 ; 87.437,55.56 87.437,56.068 ; 87.437,56.068 87.437,56.576 ; 87.437,56.068 87.945,56.068 ; 87.437,56.576 87.437,57.084 ; 87.437,56.576 87.945,56.576 ; 87.437,57.084 87.437,57.592 ; 87.437,57.084 87.945,57.084 ; 87.437,57.592 87.437,58.1 ; 87.437,57.592 87.945,57.592 ; 87.437,58.1 87.437,58.608 ; 87.437,58.1 87.945,58.1 ; 87.437,58.608 87.437,59.116 ; 87.437,58.608 87.945,58.608 ; 87.437,59.116 87.437,59.624 ; 87.437,59.116 87.945,59.116 ; 87.437,59.624 87.437,60.132 ; 87.437,59.624 87.945,59.624 ; 87.437,60.132 87.437,60.64 ; 87.437,60.132 87.945,60.132 ; 87.437,60.64 87.437,61.148 ; 87.437,60.64 87.945,60.64 ; 87.437,61.148 87.437,61.656 ; 87.437,61.148 87.945,61.148 ; 87.437,61.656 87.437,62.164 ; 87.437,61.656 87.945,61.656 ; 87.437,62.164 87.945,62.164 ; 87.464,55.052 87.945,55.533 ; 87.481,23.556 cw(c86.167,23.241) 87.484,23.545 cw(c86.167,23.241) 87.519,23.241 cw(c86.167,23.241) 87.505,23.048 ; 87.481,23.556 87.945,23.556 ; 87.505,23.048 87.945,23.048 ; 87.599,37.78 87.945,37.78 ; 87.599,37.78 87.945,38.126 ; 87.945,20.889 87.945,21.016 ; 87.945,20.889 88.453,20.889 ; 87.945,21.016 87.945,21.524 ; 87.945,21.016 88.453,21.016 ; 87.945,21.524 87.945,22.032 ; 87.945,21.524 88.453,21.524 ; 87.945,22.032 87.945,22.54 ; 87.945,22.032 88.453,22.032 ; 87.945,22.54 87.945,23.048 ; 87.945,22.54 CN2.5@88.453,22.54 ; 87.945,23.048 CN2.5@88.453,23.048 ; 87.945,23.048 87.945,23.556 ; 87.945,23.556 87.945,24.064 ; 87.945,23.556 CN2.5@88.453,23.556 ; 87.945,24.064 87.945,24.572 ; 87.945,24.064 88.453,24.064 ; 87.945,24.572 87.945,25.08 ; 87.945,24.572 88.453,24.572 ; 87.945,25.08 87.945,25.588 ; 87.945,25.08 88.453,25.08 ; 87.945,25.588 87.945,26.096 ; 87.945,25.588 pad.@88.453,25.588 ; 87.945,26.096 87.945,26.604 ; 87.945,26.096 pad.@88.453,26.096 ; 87.945,26.604 87.945,27.112 ; 87.945,26.604 88.453,26.604 ; 87.945,27.112 87.945,27.62 ; 87.945,27.112 88.453,27.112 ; 87.945,27.62 87.945,28.128 ; 87.945,27.62 88.453,27.62 ; 87.945,28.128 87.945,28.636 ; 87.945,28.128 88.453,28.128 ; 87.945,28.636 87.945,29.144 ; 87.945,28.636 pad.@88.453,28.636 ; 87.945,29.144 87.945,29.652 ; 87.945,29.144 pad.@88.453,29.144 ; 87.945,29.652 87.945,30.16 ; 87.945,29.652 88.453,29.652 ; 87.945,30.16 87.945,30.668 ; 87.945,30.16 88.453,30.16 ; 87.945,30.668 87.945,31.176 ; 87.945,30.668 88.453,30.668 ; 87.945,31.176 87.945,31.684 ; 87.945,31.176 88.453,31.176 ; 87.945,31.684 87.945,32.192 ; 87.945,31.684 88.453,31.684 ; 87.945,32.192 87.945,32.7 ; 87.945,32.192 88.453,32.192 ; 87.945,32.7 87.945,33.208 ; 87.945,32.7 88.453,32.7 ; 87.945,33.208 87.945,33.716 ; 87.945,33.208 88.453,33.208 ; 87.945,33.716 87.945,34.224 ; 87.945,33.716 pad.@88.453,33.716 ; 87.945,34.224 87.945,34.732 ; 87.945,34.224 88.453,34.224 ; 87.945,34.732 87.945,35.24 ; 87.945,34.732 88.453,34.732 ; 87.945,35.24 87.945,35.748 ; 87.945,35.24 pad.@88.453,35.24 ; 87.945,35.748 87.945,36.256 ; 87.945,35.748 88.453,35.748 ; 87.945,36.256 87.945,36.764 ; 87.945,36.256 88.453,36.256 ; 87.945,36.764 87.945,37.272 ; 87.945,36.764 pad.@88.453,36.764 ; 87.945,37.272 87.945,37.78 ; 87.945,37.272 88.453,37.272 ; 87.945,37.78 87.945,38.126 ; 87.945,37.78 pad.@88.453,37.78 ; 87.945,38.126 88.107,38.288 ; 87.945,55.533 87.945,55.56 ; 87.945,55.533 87.972,55.56 ; 87.945,55.56 87.945,56.068 ; 87.945,55.56 87.972,55.56 ; 87.945,56.068 88.453,56.068 ; 87.945,56.068 87.945,56.576 ; 87.945,56.576 88.453,56.576 ; 87.945,56.576 87.945,57.084 ; 87.945,57.084 88.453,57.084 ; 87.945,57.084 87.945,57.592 ; 87.945,57.592 87.945,58.1 ; 87.945,57.592 88.453,57.592 ; 87.945,58.1 88.453,58.1 ; 87.945,58.1 87.945,58.608 ; 87.945,58.608 87.945,59.116 ; 87.945,58.608 88.453,58.608 ; 87.945,59.116 88.453,59.116 ; 87.945,59.116 87.945,59.624 ; 87.945,59.624 87.945,60.132 ; 87.945,59.624 88.453,59.624 ; 87.945,60.132 87.945,60.64 ; 87.945,60.132 88.453,60.132 ; 87.945,60.64 88.453,60.64 ; 87.945,60.64 87.945,61.148 ; 87.945,61.148 87.945,61.656 ; 87.945,61.148 88.453,61.148 ; 87.945,61.656 88.453,61.656 ; 87.945,61.656 87.945,62.164 ; 87.945,62.164 88.453,62.164 ; 87.972,55.56 88.36,55.948 ; 88.107,38.288 pad.@88.453,38.288 ; 88.107,38.288 88.261,38.443 88.453,38.634 ; 88.36,55.948 cw(c88.875,55.433) 88.453,56.027 ; 88.36,55.948 cw(c88.875,55.433) 88.453,56.027 ; 88.453,20.889 88.453,21.016 ; 88.453,20.889 88.961,20.889 ; 88.453,21.016 88.453,21.524 ; 88.453,21.016 88.961,21.016 ; 88.453,21.524 88.453,22.032 ; 88.453,21.524 pad.@88.961,21.524 ; 88.453,22.032 CN2.5@88.453,22.54 ; 88.453,22.032 88.961,22.032 ; CN2.5@88.453,22.54 CN2.5@88.453,23.048 ; CN2.5@88.453,22.54 CN2.5@88.961,22.54 ; CN2.5@88.453,23.048 CN2.5@88.453,23.556 ; CN2.5@88.453,23.048 CN2.5@88.961,23.048 ; CN2.5@88.453,23.556 88.453,24.064 ; CN2.5@88.453,23.556 CN2.5@88.961,23.556 ; 88.453,24.064 88.453,24.572 ; 88.453,24.064 88.961,24.064 ; 88.453,24.572 88.453,25.08 ; 88.453,24.572 88.961,24.572 ; 88.453,25.08 pad.@88.453,25.588 ; 88.453,25.08 88.961,25.08 ; pad.@88.453,25.588 pad.@88.453,26.096 ; pad.@88.453,25.588 pad.@88.961,25.588 ; pad.@88.453,26.096 88.453,26.604 ; pad.@88.453,26.096 88.961,26.096 ; 88.453,26.604 88.453,27.112 ; 88.453,26.604 88.961,26.604 ; 88.453,27.112 88.453,27.62 ; 88.453,27.112 88.961,27.112 ; 88.453,27.62 88.453,28.128 ; 88.453,27.62 88.961,27.62 ; 88.453,28.128 pad.@88.453,28.636 ; 88.453,28.128 88.961,28.128 ; pad.@88.453,28.636 pad.@88.453,29.144 ; pad.@88.453,28.636 88.961,28.636 ; pad.@88.453,29.144 88.453,29.652 ; pad.@88.453,29.144 88.961,29.144 ; 88.453,29.652 88.453,30.16 ; 88.453,29.652 88.961,29.652 ; 88.453,30.16 88.453,30.668 ; 88.453,30.16 88.961,30.16 ; 88.453,30.668 88.453,31.176 ; 88.453,30.668 88.961,30.668 ; 88.453,31.176 88.453,31.684 ; 88.453,31.176 88.961,31.176 ; 88.453,31.684 88.453,32.192 ; 88.453,31.684 88.961,31.684 ; 88.453,32.192 88.453,32.7 ; 88.453,32.192 88.961,32.192 ; 88.453,32.7 88.453,33.208 ; 88.453,32.7 88.961,32.7 ; 88.453,33.208 pad.@88.453,33.716 ; 88.453,33.208 88.961,33.208 ; pad.@88.453,33.716 88.453,34.224 ; pad.@88.453,33.716 pad.@88.961,33.716 ; 88.453,34.224 88.453,34.732 ; 88.453,34.224 88.961,34.224 ; 88.453,34.732 pad.@88.453,35.24 ; 88.453,34.732 88.961,34.732 ; pad.@88.453,35.24 88.453,35.748 ; pad.@88.453,35.24 88.961,35.24 ; 88.453,35.748 88.453,36.256 ; 88.453,35.748 88.961,35.748 ; 88.453,36.256 pad.@88.453,36.764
